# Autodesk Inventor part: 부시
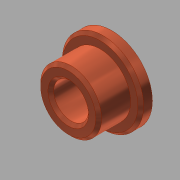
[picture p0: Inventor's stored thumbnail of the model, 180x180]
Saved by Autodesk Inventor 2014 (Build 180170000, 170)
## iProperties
Created: 2016-02
Part Number: 부시
Material: 강철, 연강
Document SubType Name: Modeling
Designer: test
Density: 1 g/cm^3
Appearance: 금속 1400F 열
Author: test
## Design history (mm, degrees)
sketch "스케치1"
  geometry: C1 r 14 at (0, 0); C2 r 10.5 at (0, 0); 1 further point
  constraints: 2 centre point, 2 coincident
  dimensions: "d0" = 28 diameter of C1; "d1" = 21 diameter of C2
extrude "돌출1" new body sketch "스케치1" distance "d2" = 4; taper "d3" = 0 deg
extrude "돌출2" join sketch "스케치1" distance "d4" = 11; taper "d5" = 0 deg
hole "구멍1" diameter "d8" = 12; stored, may be unused: countersink angle "d12" = 90 deg, drill point angle "d14" = 118 deg; dims "d6" = 10, "d7" = 10, "d9" = 6, "d10" = 4, "d11" = 2, "d13" = 8
chamfer "모따기1" distance "d15" = 1; stored, may be unused: second distance "d16" = 2, angle "d17" = 45 deg
chamfer "모따기2" distance "d18" = 1; stored, may be unused: second distance "d19" = 2, angle "d20" = 45 deg
node "솔리드1"
